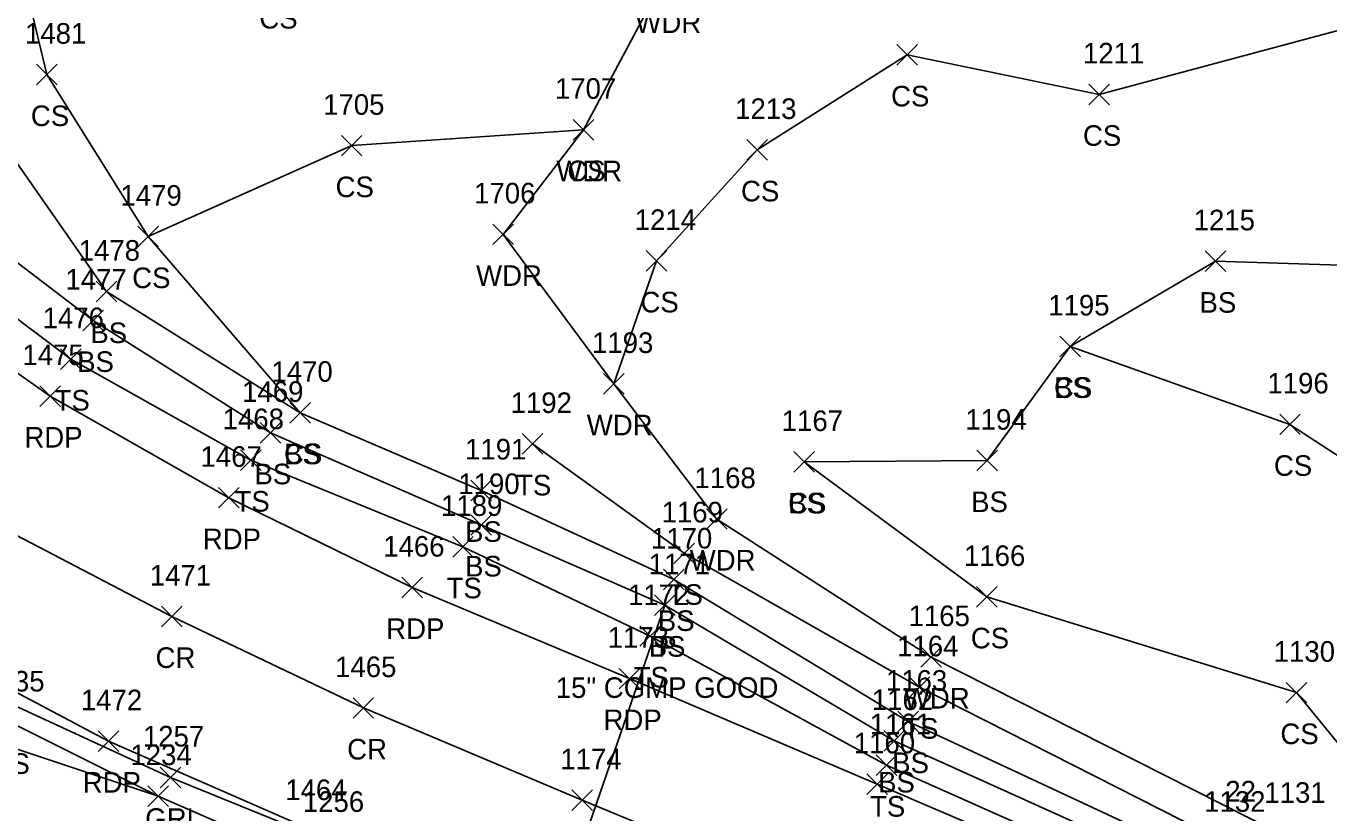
# Model space of a CAD drawing. Extents: x 1499292 to 1501024, y 534584 to 538043.
# Drawn here: x 1499970.1 to 1500096.6, y 537488 to 537564.4 of the extents above; entities that cross this region are included whole.
import ezdxf

# ---------------------------------------------------------------- set-up
doc = ezdxf.new("R2010")
doc.units = 0
for name, color, linetype in [('C_I', 7, 'Continuous'), ('D_A', 7, 'Continuous'), ('D_C', 7, 'Continuous'), ('D_I', 7, 'Continuous'), ('D_TIC', 7, 'Continuous'), ('DCP', 7, 'Continuous'), ('L_A', 7, 'Continuous'), ('L_I', 7, 'Continuous'), ('L_TIC', 7, 'Continuous'), ('LAWA', 7, 'Continuous'), ('LELB', 7, 'Continuous'), ('P_A', 7, 'Continuous'), ('P_I', 7, 'Continuous'), ('P_TIC', 7, 'Continuous'), ('PET', 7, 'Continuous'), ('PRC', 7, 'Continuous'), ('R_A', 7, 'Continuous'), ('R_I', 7, 'Continuous'), ('R_TIC', 7, 'Continuous'), ('RGR', 7, 'Continuous')]:
    doc.layers.add(name, color=color, linetype=linetype)

msp = doc.modelspace()

# ---------------------------------------------------------------- linework, layer by layer
at = {"layer": 'D_TIC'}
for points in [[(1500031.11, 537507.21), (1500033.11, 537509.21)], [(1500033.11, 537507.21), (1500031.11, 537509.21)]]:
    msp.add_lwpolyline(points, dxfattribs=at)
at = {"layer": 'DCP'}
msp.add_lwpolyline([(1500032.11, 537508.21), (1500018.89, 537469.8)], dxfattribs=at)
at = {"layer": 'L_TIC'}
for points in [[(1500054.63, 537560.64), (1500056.63, 537562.64)], [(1500056.63, 537560.64), (1500054.63, 537562.64)], [(1499971.16, 537558.73), (1499973.16, 537560.73)], [(1499973.16, 537558.73), (1499971.16, 537560.73)], [(1500073.25, 537556.81), (1500075.25, 537558.81)], [(1500075.25, 537556.81), (1500073.25, 537558.81)], [(1500023.22, 537553.38), (1500025.22, 537555.38)], [(1500025.22, 537553.38), (1500023.22, 537555.38)], [(1500023.22, 537553.38), (1500025.22, 537555.38)], [(1500025.22, 537553.38), (1500023.22, 537555.38)], [(1500000.73, 537551.83), (1500002.73, 537553.83)], [(1500002.73, 537551.83), (1500000.73, 537553.83)], [(1500040.07, 537551.42), (1500042.07, 537553.42)], [(1500042.07, 537551.42), (1500040.07, 537553.42)], [(1500015.43, 537543.22), (1500017.43, 537545.22)], [(1500017.43, 537543.22), (1500015.43, 537545.22)], [(1499980.99, 537543), (1499982.99, 537545)], [(1499982.99, 537543), (1499980.99, 537545)], [(1499980.99, 537543), (1499982.99, 537545)], [(1499982.99, 537543), (1499980.99, 537545)], [(1500030.31, 537540.64), (1500032.31, 537542.64)], [(1500032.31, 537540.64), (1500030.31, 537542.64)], [(1500084.56, 537540.61), (1500086.56, 537542.61)], [(1500086.56, 537540.61), (1500084.56, 537542.61)], [(1499976.93, 537537.66), (1499978.93, 537539.66)], [(1499978.93, 537537.66), (1499976.93, 537539.66)], [(1499975.65, 537534.86), (1499977.65, 537536.86)], [(1499977.65, 537534.86), (1499975.65, 537536.86)], [(1500070.44, 537532.34), (1500072.44, 537534.34)], [(1500072.44, 537532.34), (1500070.44, 537534.34)], [(1500070.44, 537532.34), (1500072.44, 537534.34)], [(1500072.44, 537532.34), (1500070.44, 537534.34)], [(1499973.49, 537531.11), (1499975.49, 537533.11)], [(1499975.49, 537531.11), (1499973.49, 537533.11)], [(1500026.18, 537528.7), (1500028.18, 537530.7)], [(1500028.18, 537528.7), (1500026.18, 537530.7)], [(1499995.72, 537525.9), (1499997.72, 537527.9)], [(1499997.72, 537525.9), (1499995.72, 537527.9)], [(1499995.72, 537525.9), (1499997.72, 537527.9)], [(1499997.72, 537525.9), (1499995.72, 537527.9)], [(1500091.78, 537524.77), (1500093.78, 537526.77)], [(1500093.78, 537524.77), (1500091.78, 537526.77)], [(1499992.85, 537523.95), (1499994.85, 537525.95)], [(1499994.85, 537523.95), (1499992.85, 537525.95)], [(1500018.27, 537522.87), (1500020.27, 537524.87)], [(1500020.27, 537522.87), (1500018.27, 537524.87)], [(1499990.95, 537521.3), (1499992.95, 537523.3)], [(1499992.95, 537521.3), (1499990.95, 537523.3)], [(1500044.64, 537521.12), (1500046.64, 537523.12)], [(1500046.64, 537521.12), (1500044.64, 537523.12)], [(1500044.64, 537521.12), (1500046.64, 537523.12)], [(1500046.64, 537521.12), (1500044.64, 537523.12)], [(1500062.4, 537521.25), (1500064.4, 537523.25)], [(1500064.4, 537521.25), (1500062.4, 537523.25)], [(1500013.29, 537518.36), (1500015.29, 537520.36)], [(1500015.29, 537518.36), (1500013.29, 537520.36)], [(1500036.17, 537515.58), (1500038.17, 537517.58)], [(1500038.17, 537515.58), (1500036.17, 537517.58)], [(1500013.29, 537515), (1500015.29, 537517)], [(1500015.29, 537515), (1500013.29, 537517)], [(1500011.53, 537512.88), (1500013.53, 537514.88)], [(1500013.53, 537512.88), (1500011.53, 537514.88)], [(1500032.98, 537512.25), (1500034.98, 537514.25)], [(1500034.98, 537512.25), (1500032.98, 537514.25)], [(1500031.99, 537509.71), (1500033.99, 537511.71)], [(1500033.99, 537509.71), (1500031.99, 537511.71)], [(1500062.37, 537508.02), (1500064.37, 537510.02)], [(1500064.37, 537508.02), (1500062.37, 537510.02)], [(1500031.11, 537507.21), (1500033.11, 537509.21)], [(1500033.11, 537507.21), (1500031.11, 537509.21)], [(1500029.68, 537504.22), (1500031.68, 537506.22)], [(1500031.68, 537504.22), (1500029.68, 537506.22)], [(1500056.95, 537502.18), (1500058.95, 537504.18)], [(1500058.95, 537502.18), (1500056.95, 537504.18)], [(1500055.84, 537499.25), (1500057.84, 537501.25)], [(1500057.84, 537499.25), (1500055.84, 537501.25)], [(1500092.41, 537498.72), (1500094.41, 537500.72)], [(1500094.41, 537498.72), (1500092.41, 537500.72)], [(1500054.74, 537495.91), (1500056.74, 537497.91)], [(1500056.74, 537495.91), (1500054.74, 537497.91)], [(1500053.37, 537494.03), (1500055.37, 537496.03)], [(1500055.37, 537494.03), (1500053.37, 537496.03)], [(1500052.62, 537491.68), (1500054.62, 537493.68)], [(1500054.62, 537491.68), (1500052.62, 537493.68)], [(1499981.95, 537488.68), (1499983.95, 537490.68)], [(1499983.95, 537488.68), (1499981.95, 537490.68)], [(1499981.95, 537488.68), (1499983.95, 537490.68)], [(1499983.95, 537488.68), (1499981.95, 537490.68)]]:
    msp.add_lwpolyline(points, dxfattribs=at)
at = {"layer": 'LAWA'}
msp.add_lwpolyline([(1500296.25, 537345.3), (1500256.73, 537378.82), (1500246.41, 537388.79), (1500239.52, 537392.77), (1500228.03, 537398.5), (1500203.66, 537420.68), (1500174.13, 537441.21), (1500133.61, 537461.8), (1500091.85, 537486.02), (1500057.95, 537503.18), (1500037.17, 537516.58), (1500027.18, 537529.7), (1500016.43, 537544.22), (1500024.22, 537554.38), (1500031.9, 537568.77)], dxfattribs=at)
at = {"layer": 'LELB'}
for points in [[(1499982.95, 537489.68), (1499966.99, 537494.97), (1499951.63, 537501.69), (1499942.17, 537508.92), (1499936.88, 537512.97), (1499930.43, 537522.3), (1499913.7, 537537.04), (1499897.54, 537554.09), (1499883.23, 537576.21), (1499873.98, 537589.18), (1499855.89, 537613.14), (1499849.42, 537619.3), (1499842.66, 537629.92), (1499836.97, 537639.79), (1499825.94, 537654.56), (1499819.31, 537659.47)], [(1500290.71, 537339.51), (1500254.04, 537373.68), (1500224.98, 537395.42), (1500200.73, 537412.86), (1500170.41, 537433.92), (1500131.37, 537455.4), (1500083.47, 537479.37), (1500053.62, 537492.68), (1500030.68, 537505.22), (1500012.53, 537513.88), (1499991.95, 537522.3), (1499974.49, 537532.11), (1499955.61, 537546.28), (1499937.72, 537561.94), (1499940.61, 537580.36), (1499943.98, 537590.51), (1499964.26, 537598.71), (1499981.02, 537608.13), (1500000.32, 537612.94)], [(1500292.43, 537341.34), (1500255.06, 537375.07), (1500226.32, 537396.72), (1500201.26, 537414.48), (1500171.22, 537435.38), (1500132.04, 537457.48), (1500085.68, 537482.93), (1500055.74, 537496.91), (1500032.99, 537510.71), (1500014.29, 537519.36), (1499996.72, 537526.9), (1499977.93, 537538.66), (1499965.7, 537556.17), (1499963.9, 537570.61), (1499969.57, 537590.89), (1499978.12, 537601.79)], [(1499996.72, 537526.9), (1499981.99, 537544), (1499972.16, 537559.73), (1499969.38, 537571.36), (1499979.56, 537592.44)], [(1500291.4, 537340.15), (1500254.56, 537374.3), (1500225.71, 537395.92), (1500201.33, 537413.51), (1500170.9, 537434.45), (1500131.84, 537456.62), (1500084.75, 537481.32), (1500054.37, 537495.03), (1500032.11, 537508.21), (1500014.29, 537516), (1499993.85, 537524.95), (1499976.65, 537535.86), (1499959.1, 537549.21), (1499939.76, 537563.39), (1499940.61, 537580.36)], [(1500071.44, 537533.34), (1500092.78, 537525.77), (1500113.32, 537512.39), (1500125.76, 537504.08), (1500142.13, 537491.72), (1500147.83, 537500.24), (1500145.6, 537512.61), (1500170.24, 537505.74), (1500161.32, 537537.08), (1500144.36, 537544.45), (1500125.84, 537549.67), (1500104.94, 537566.02), (1500074.25, 537557.81), (1500055.63, 537561.64), (1500041.07, 537552.42), (1500031.31, 537541.64)], [(1499981.99, 537544), (1500001.73, 537552.83), (1500024.22, 537554.38)], [(1500031.31, 537541.64), (1500027.18, 537529.7)], [(1500045.64, 537522.12), (1500063.4, 537522.25), (1500071.44, 537533.34), (1500085.56, 537541.61), (1500098.67, 537541.18)], [(1500294.64, 537343.13), (1500255.06, 537375.07), (1500255.51, 537377.72), (1500228.03, 537398.5), (1500201.95, 537416.01), (1500172.91, 537436.91), (1500133.61, 537461.8), (1500086.58, 537485.15), (1500056.84, 537500.25), (1500033.98, 537513.25), (1500019.27, 537523.87)], [(1500233.37, 537402.87), (1500206.14, 537427.76), (1500177.42, 537447.25), (1500138.31, 537473.63), (1500103.59, 537487.28), (1500093.41, 537499.72), (1500063.37, 537509.02), (1500045.64, 537522.12)], [(1500131.44, 537420.15), (1500118.57, 537428.9), (1500071.28, 537451.3), (1500039.9, 537462.51), (1500019.6, 537472.93), (1499998.36, 537482.93), (1499982.95, 537489.68), (1499968.67, 537496.83), (1499953.48, 537503.61), (1499943.52, 537510.2)]]:
    msp.add_lwpolyline(points, dxfattribs=at)
at = {"layer": 'P_TIC'}
for points in [[(1499971.48, 537527.52), (1499973.48, 537529.52)], [(1499973.48, 537527.52), (1499971.48, 537529.52)], [(1499988.8, 537517.65), (1499990.8, 537519.65)], [(1499990.8, 537517.65), (1499988.8, 537519.65)], [(1500006.59, 537508.93), (1500008.59, 537510.93)], [(1500008.59, 537508.93), (1500006.59, 537510.93)], [(1499983.27, 537506.12), (1499985.27, 537508.12)], [(1499985.27, 537506.12), (1499983.27, 537508.12)], [(1500027.69, 537500.08), (1500029.69, 537502.08)], [(1500029.69, 537500.08), (1500027.69, 537502.08)], [(1500001.86, 537497.23), (1500003.86, 537499.23)], [(1500003.86, 537497.23), (1500001.86, 537499.23)], [(1499977.14, 537494.01), (1499979.14, 537496.01)], [(1499979.14, 537494.01), (1499977.14, 537496.01)], [(1500051.71, 537489.83), (1500053.71, 537491.83)], [(1500053.71, 537489.83), (1500051.71, 537491.83)], [(1500023.1, 537488.28), (1500025.1, 537490.28)], [(1500025.1, 537488.28), (1500023.1, 537490.28)]]:
    msp.add_lwpolyline(points, dxfattribs=at)
at = {"layer": 'PET'}
for points in [[(1500289.78, 537338.29), (1500253.04, 537372.98), (1500224.75, 537395.04), (1500200.64, 537412.65), (1500169.79, 537433.28), (1500131.37, 537455.4), (1500082.94, 537477.86), (1500052.71, 537490.83), (1500028.69, 537501.08), (1500007.59, 537509.93), (1499989.8, 537518.65), (1499972.48, 537528.52), (1499952.08, 537542.88), (1499935.46, 537557.31), (1499909.99, 537586.35), (1499888.96, 537613.55)], [(1500270.13, 537322.4), (1500238.22, 537353.72), (1500209.42, 537377.09), (1500189.13, 537391.85), (1500154.51, 537414.13), (1500120.36, 537433.62), (1500072.03, 537456.11), (1500021.37, 537476.64), (1499998.02, 537486.29), (1499978.14, 537495.01), (1499958.62, 537505.35), (1499935.09, 537521.93), (1499915.79, 537539.45), (1499898.17, 537558.63), (1499884.72, 537577.02)]]:
    msp.add_lwpolyline(points, dxfattribs=at)
at = {"layer": 'PRC'}
msp.add_lwpolyline([(1500278.96, 537330.13), (1500245.16, 537363.32), (1500217.07, 537386.35), (1500194.78, 537402.07), (1500161.59, 537424.07), (1500124.89, 537444.32), (1500077.4, 537466.83), (1500048.03, 537479.39), (1500024.1, 537489.28), (1500002.86, 537498.23), (1499984.27, 537507.12), (1499965.54, 537516.89), (1499943.1, 537532.26), (1499924.7, 537548.4), (1499906.7, 537567.9), (1499892.97, 537586.05), (1499884.57, 537597.67), (1499868.24, 537621.71), (1499849.2, 537650.1), (1499837.66, 537665.34), (1499832.02, 537672.42)], dxfattribs=at)
at = {"layer": 'R_TIC'}
for points in [[(1499983.16, 537490.49), (1499985.16, 537492.49)], [(1499985.16, 537490.49), (1499983.16, 537492.49)]]:
    msp.add_lwpolyline(points, dxfattribs=at)
at = {"layer": 'RGR'}
msp.add_lwpolyline([(1500269.09, 537321.92), (1500237.75, 537353.24), (1500209.1, 537376.73), (1500188.83, 537391.14), (1500154.15, 537413.64), (1500120.04, 537433), (1500071.71, 537455.6), (1500042.55, 537467.65), (1500021.13, 537476.12), (1499999.74, 537485.14), (1499984.16, 537491.49), (1499962.3, 537501.56), (1499943.52, 537510.2), (1499936.88, 537512.97), (1499926.59, 537517.73)], dxfattribs=at)

# ---------------------------------------------------------------- texts
at = {"layer": 'C_I'}
msp.add_text('22', height=2, dxfattribs=at).set_placement((1500086.5, 537489.15))
at = {"layer": 'D_A'}
msp.add_text('P', height=2, dxfattribs=at).set_placement((1500031.48, 537503.21))
at = {"layer": 'D_C'}
msp.add_text('15" CGMP GOOD', height=2, dxfattribs=at).set_placement((1500021.53, 537499.21))
at = {"layer": 'D_I'}
msp.add_text('1171', height=2, dxfattribs=at).set_placement((1500030.55, 537511.21))
at = {"layer": 'L_A'}
for s, p in [('CS', (1499992.77, 537564.2)), ('WDR', (1500029.26, 537563.77)), ('CS', (1500054.07, 537556.64)), ('CS', (1499970.6, 537554.73)), ('CS', (1500072.69, 537552.81)), ('CS', (1500022.66, 537549.38)), ('WDR', (1500021.58, 537549.38)), ('CS', (1500000.17, 537547.83)), ('CS', (1500039.51, 537547.42)), ('CS', (1499980.43, 537539)), ('CS', (1499980.43, 537539)), ('WDR', (1500013.8, 537539.22)), ('CS', (1500029.75, 537536.64)), ('BS', (1500084, 537536.61)), ('BS', (1499976.37, 537533.66)), ('BS', (1499975.09, 537530.86)), ('CS', (1500069.88, 537528.34)), ('BS', (1500069.88, 537528.34)), ('TS', (1499972.9, 537527.11)), ('WDR', (1500024.54, 537524.7)), ('CS', (1499995.16, 537521.9)), ('BS', (1499995.16, 537521.9)), ('CS', (1500091.22, 537520.77)), ('BS', (1499992.29, 537519.95)), ('TS', (1500017.68, 537518.87)), ('TS', (1499990.36, 537517.3)), ('CS', (1500044.08, 537517.12)), ('BS', (1500044.08, 537517.12)), ('BS', (1500061.84, 537517.25)), ('BS', (1500012.73, 537514.36)), ('WDR', (1500034.53, 537511.58)), ('BS', (1500012.73, 537511)), ('TS', (1500010.94, 537508.88)), ('TS', (1500032.39, 537508.25)), ('BS', (1500031.43, 537505.71)), ('CS', (1500061.81, 537504.02)), ('BS', (1500030.55, 537503.21)), ('TS', (1500029.09, 537500.22)), ('WDR', (1500055.31, 537498.18)), ('TS', (1500055.25, 537495.25)), ('CS', (1500091.85, 537494.72)), ('TS', (1499967.08, 537491.83)), ('BS', (1500054.18, 537491.91)), ('BS', (1500052.81, 537490.03)), ('TS', (1500052.03, 537487.68))]:
    msp.add_text(s, height=2, dxfattribs=at).set_placement(p)
at = {"layer": 'L_I'}
for s, p in [('1481', (1499970.03, 537562.73)), ('1211', (1500072.69, 537560.81)), ('1707', (1500021.45, 537557.38)), ('1707', (1500021.45, 537557.38)), ('1705', (1499998.96, 537555.83)), ('1213', (1500038.94, 537555.42)), ('1479', (1499979.29, 537547)), ('1479', (1499979.29, 537547)), ('1706', (1500013.61, 537547.22)), ('1214', (1500029.19, 537544.64)), ('1215', (1500083.43, 537544.61)), ('1478', (1499975.24, 537541.66)), ('1477', (1499973.96, 537538.86)), ('1195', (1500069.32, 537536.34)), ('1195', (1500069.32, 537536.34)), ('1476', (1499971.74, 537535.11)), ('1193', (1500025.05, 537532.7)), ('1470', (1499993.94, 537529.9)), ('1470', (1499993.94, 537529.9)), ('1469', (1499991.1, 537527.95)), ('1196', (1500090.59, 537528.77)), ('1192', (1500017.15, 537526.87)), ('1468', (1499989.21, 537525.3)), ('1167', (1500043.46, 537525.12)), ('1167', (1500043.46, 537525.12)), ('1194', (1500061.28, 537525.25)), ('1191', (1500012.73, 537522.36)), ('1168', (1500034.99, 537519.58)), ('1190', (1500012.08, 537519)), ('1189', (1500010.4, 537516.88)), ('1169', (1500031.8, 537516.25)), ('1170', (1500030.77, 537513.71)), ('1166', (1500061.15, 537512.02)), ('1171', (1500030.55, 537511.21)), ('1172', (1500028.55, 537508.22)), ('1165', (1500055.77, 537506.18)), ('1164', (1500054.66, 537503.25)), ('1130', (1500091.2, 537502.72)), ('1235', (1499965.98, 537499.83)), ('1163', (1500053.57, 537499.91)), ('1162', (1500052.2, 537498.03)), ('1161', (1500052.01, 537495.68)), ('1234', (1499980.26, 537492.68)), ('1234', (1499980.26, 537492.68)), ('1131', (1500090.29, 537489.02)), ('1132', (1500084.45, 537488.15))]:
    msp.add_text(s, height=2, dxfattribs=at).set_placement(p)
at = {"layer": 'P_A'}
for s, p in [('RDP', (1499969.97, 537523.52)), ('RDP', (1499987.28, 537513.65)), ('RDP', (1500005.08, 537504.93)), ('CR', (1499982.7, 537502.12)), ('RDP', (1500026.17, 537496.08)), ('CR', (1500001.29, 537493.23)), ('RDP', (1499975.63, 537490.01))]:
    msp.add_text(s, height=2, dxfattribs=at).set_placement(p)
at = {"layer": 'P_I'}
for s, p in [('1475', (1499969.78, 537531.52)), ('1467', (1499987.06, 537521.65)), ('1466', (1500004.79, 537512.93)), ('1471', (1499982.14, 537510.12)), ('1173', (1500026.56, 537504.08)), ('1465', (1500000.12, 537501.23)), ('1472', (1499975.45, 537498.01)), ('1160', (1500050.45, 537493.83)), ('1174', (1500021.97, 537492.28)), ('1464', (1499995.28, 537489.29))]:
    msp.add_text(s, height=2, dxfattribs=at).set_placement(p)
at = {"layer": 'R_A'}
msp.add_text('GRL', height=2, dxfattribs=at).set_placement((1499981.7, 537486.49))
at = {"layer": 'R_I'}
for s, p in [('1257', (1499981.47, 537494.49)), ('1256', (1499996.99, 537488.14))]:
    msp.add_text(s, height=2, dxfattribs=at).set_placement(p)

doc.saveas('drawing.dxf')
